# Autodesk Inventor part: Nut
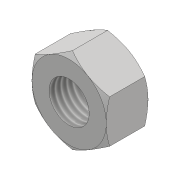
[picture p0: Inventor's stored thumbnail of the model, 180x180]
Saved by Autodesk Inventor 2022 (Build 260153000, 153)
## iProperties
Created: 2016-05
Part Number: Nut
Material: Generic
Document SubType Name: Modeling
Designer: CADCIM
Density: 1 g/cm^3
Appearance: Default
Author: CADCIM
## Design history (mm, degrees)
sketch "Sketch1"
  geometry: L1 (9.6, -5.543)-(0, -11.085); L2 (0, -11.085)-(-9.6, -5.543); L3 (-9.6, -5.543)-(-9.6, 5.543); L4 (-9.6, 5.543)-(0, 11.085); L5 (0, 11.085)-(9.6, 5.543); L6 (9.6, 5.543)-(9.6, -5.543); 2 further points
  constraints: 12 end point, 1 coincident, 1 vertical alignment, 13 other
  dimensions: "d0" = 19.2 distance between parallel lines of L3 L6
extrude "Extrusion1" new body sketch "Sketch1" distance "d1" = 10.8; taper "d2" = 0 deg
sketch "Sketch2"
  geometry: L1 (0, 11.085)-(-9.6, 5.543) reference; C1 r 9.6 at (0, 0); 1 further point
  constraints: 1 centre point, 1 coincident, 1 tangent
extrude "Extrusion2" sketch "Sketch2" distance "d3" = 10.8; taper "d4" = 60 deg
workplane "Work Plane1"
sketch "Sketch3"
  geometry: L1 (0, -11.085)-(9.6, -5.543) reference; C1 r 9.6 at (0, 0); 1 further point
  constraints: 1 centre point, 1 coincident, 1 tangent
extrude "Extrusion3" sketch "Sketch3" distance "d5" = 10.8; taper "d6" = 60 deg
sketch "Sketch4"
  geometry: 1 further point
hole "Hole1" diameter "d9" = 10.376; stored, may be unused: countersink angle "d13" = 90 deg, drill point angle "d15" = 118 deg; dims "d7" = 10, "d8" = 10, "d10" = 24, "d11" = 4, "d12" = 2, "d14" = 31.3
body "Solid1"
